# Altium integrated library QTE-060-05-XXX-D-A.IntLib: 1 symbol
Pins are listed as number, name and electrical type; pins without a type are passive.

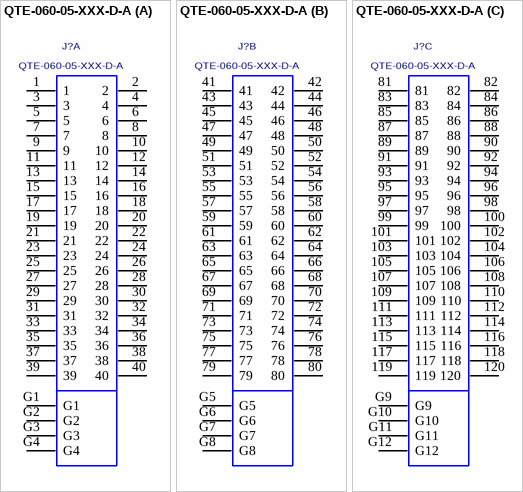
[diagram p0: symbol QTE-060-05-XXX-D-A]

## QTE-060-05-XXX-D-A
designator J?
HIGH SPEED TERMINAL STRIP, .8mm PITCH, 120 PINS.; MANUFACTURER: SAMTEC
footprint QTE-060-05-XXX-D-A
part A pins: 1, 2, 3, 4, 5, 6, 7, 8, 9, 10, 11, 12, 13, 14, 15, 16, 17, 18, 19, 20, 21, 22, 23, 24, 25, 26, 27, 28, 29, 30, 31, 32, 33, 34, 35, 36, 37, 38, 39, 40, G1, G2, G3, G4
part B pins: 41, 42, 43, 44, 45, 46, 47, 48, 49, 50, 51, 52, 53, 54, 55, 56, 57, 58, 59, 60, 61, 62, 63, 64, 65, 66, 67, 68, 69, 70, 71, 72, 73, 74, 75, 76, 77, 78, 79, 80, G5, G6, G7, G8
part C pins: 81, 82, 83, 84, 85, 86, 87, 88, 89, 90, 91, 92, 93, 94, 95, 96, 97, 98, 99, 100, 101, 102, 103, 104, 105, 106, 107, 108, 109, 110, 111, 112, 113, 114, 115, 116, 117, 118, 119, 120, G9, G10, G11, G12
